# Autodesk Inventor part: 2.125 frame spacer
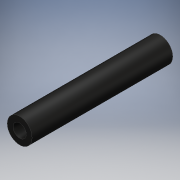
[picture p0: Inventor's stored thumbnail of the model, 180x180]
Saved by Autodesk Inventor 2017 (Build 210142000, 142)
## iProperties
Created: 2016-07
Part Number: 2.125 frame spacer
Material: Generic
Document SubType Name: Modeling
Designer: Stan
Density: 1 g/cm^3
Appearance: Glossy - Black
Author: Stan
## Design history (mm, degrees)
sketch "Sketch1"
  geometry: C1 r 4.763 at (0, 0); C2 r 2.54 at (0, 0); 1 further point
  constraints: 2 centre point, 2 coincident
  dimensions: "d0" = 9.525 diameter of C1; "d1" = 5.08 diameter of C2
extrude "Extrusion1" new body sketch "Sketch1" distance "d2" = 53.975; taper "d3" = 0 deg
body "Solid1"
